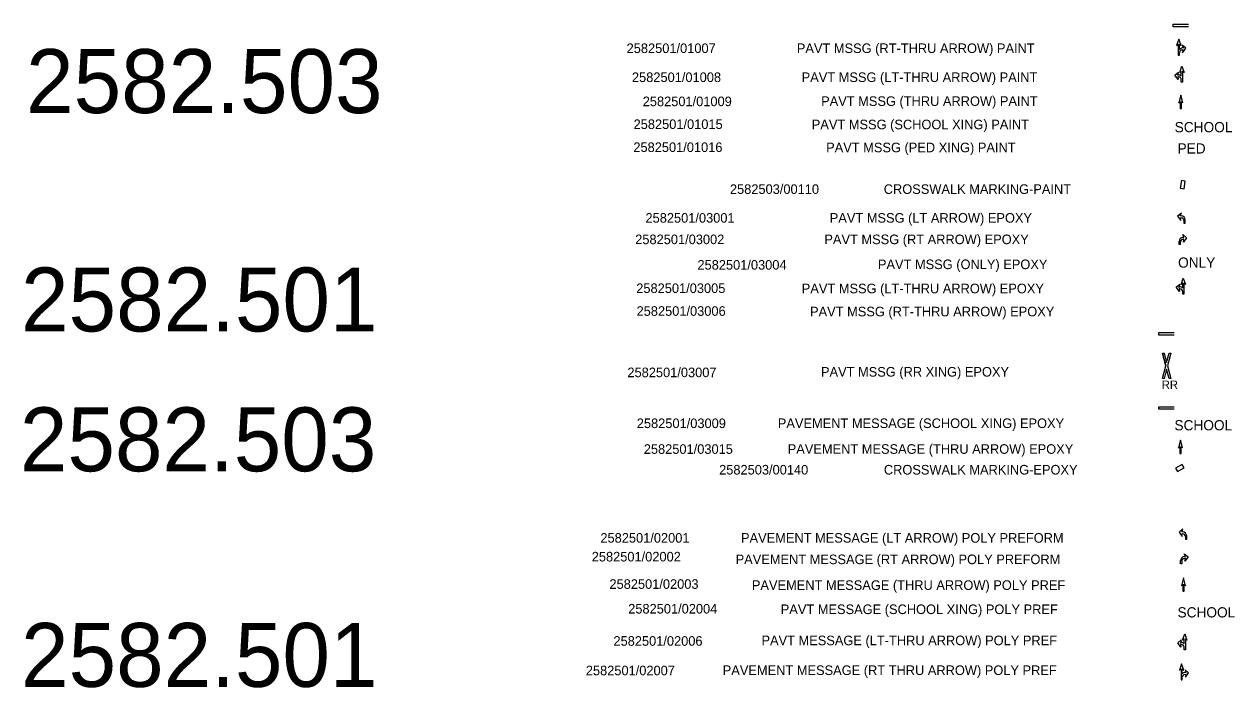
# Model space of a CAD drawing. Extents: x 2147712 to 2176316, y 2125036 to 2131746.
# Drawn here: x 2155867 to 2156814, y 2127331 to 2127850 of the extents above; entities that cross this region are included whole.
import ezdxf

# ---------------------------------------------------------------- set-up
doc = ezdxf.new("R2010")
doc.units = 0
doc.layers.add('DETAIL TXT', color=7, linetype='Continuous')
doc.layers.add('PVMT MARK', color=7, linetype='Continuous')

msp = doc.modelspace()

# ---------------------------------------------------------------- linework, layer by layer
at = {"layer": 'PVMT MARK'}
for p, q in [((2156765.38, 2127850.31), (2156777.38, 2127850.31)), ((2156765.38, 2127848.31), (2156765.38, 2127850.31)), ((2156777.38, 2127848.31), (2156765.38, 2127848.31)), ((2156769.94, 2127838.59), (2156768.21, 2127833.63)), ((2156768.21, 2127833.63), (2156769.45, 2127834.62)), ((2156769.45, 2127834.62), (2156769.45, 2127826.02)), ((2156771.68, 2127833.63), (2156769.94, 2127838.59)), ((2156770.44, 2127830.65), (2156770.44, 2127834.62)), ((2156770.44, 2127834.62), (2156771.68, 2127833.63)), ((2156772.59, 2127830.16), (2156773.25, 2127830.16)), ((2156775.4, 2127831.48), (2156772.66, 2127833.79)), ((2156772.66, 2127833.79), (2156773.32, 2127831.73)), ((2156773.32, 2127831.73), (2156772.66, 2127831.73)), ((2156772.92, 2127828.01), (2156775.4, 2127831.48)), ((2156773.25, 2127830.16), (2156772.92, 2127828.01)), ((2156769.45, 2127826.02), (2156770.44, 2127826.02)), ((2156770.44, 2127826.02), (2156770.44, 2127828.01)), ((2156766.9, 2127810.43), (2156769.65, 2127812.75)), ((2156769.65, 2127812.75), (2156768.99, 2127810.68)), ((2156770.62, 2127812.58), (2156772.36, 2127817.54)), ((2156771.86, 2127813.58), (2156770.62, 2127812.58)), ((2156771.86, 2127809.61), (2156771.86, 2127813.58)), ((2156772.36, 2127817.54), (2156774.1, 2127812.58)), ((2156774.1, 2127812.58), (2156772.86, 2127813.58)), ((2156772.86, 2127813.58), (2156772.86, 2127804.98)), ((2156769.38, 2127806.96), (2156766.9, 2127810.43)), ((2156768.99, 2127810.68), (2156769.65, 2127810.68)), ((2156769.71, 2127809.11), (2156769.05, 2127809.11)), ((2156769.05, 2127809.11), (2156769.38, 2127806.96)), ((2156771.86, 2127804.98), (2156771.86, 2127806.96)), ((2156772.86, 2127804.98), (2156771.86, 2127804.98)), ((2156769.82, 2127788.63), (2156770.95, 2127789.75)), ((2156770.95, 2127789.75), (2156770.95, 2127784.29)), ((2156770.95, 2127784.29), (2156771.94, 2127784.29)), ((2156771.94, 2127784.29), (2156771.94, 2127789.75)), ((2156771.94, 2127789.75), (2156773.06, 2127788.68)), ((2156771.97, 2127702.6), (2156768.99, 2127700.12)), ((2156768.99, 2127700.12), (2156771.47, 2127696.65)), ((2156771.06, 2127700.32), (2156771.97, 2127702.6)), ((2156771.72, 2127700.32), (2156771.06, 2127700.32)), ((2156771.47, 2127696.65), (2156771.06, 2127698.77)), ((2156771.06, 2127698.77), (2156771.72, 2127698.77)), ((2156773.95, 2127696.65), (2156773.95, 2127694.67)), ((2156773.95, 2127694.67), (2156774.94, 2127694.67)), ((2156774.94, 2127694.67), (2156774.94, 2127697.15)), ((2156770.08, 2127677.87), (2156770.08, 2127680.35)), ((2156771.08, 2127679.85), (2156771.08, 2127677.87)), ((2156773.96, 2127683.52), (2156773.06, 2127685.8)), ((2156773.06, 2127685.8), (2156776.04, 2127683.32)), ((2156773.3, 2127683.52), (2156773.96, 2127683.52)), ((2156773.96, 2127681.97), (2156773.3, 2127681.97)), ((2156776.04, 2127683.32), (2156773.56, 2127679.85)), ((2156773.56, 2127679.85), (2156773.96, 2127681.97)), ((2156771.08, 2127677.87), (2156770.08, 2127677.87)), ((2156771.7, 2127646.79), (2156773.43, 2127651.75)), ((2156773.43, 2127651.75), (2156775.17, 2127646.79)), ((2156767.97, 2127644.64), (2156770.72, 2127646.96)), ((2156770.45, 2127641.17), (2156767.97, 2127644.64)), ((2156770.72, 2127646.96), (2156770.06, 2127644.89)), ((2156770.06, 2127644.89), (2156770.72, 2127644.89)), ((2156770.79, 2127643.32), (2156770.12, 2127643.32)), ((2156770.12, 2127643.32), (2156770.45, 2127641.17)), ((2156772.94, 2127647.78), (2156771.7, 2127646.79)), ((2156772.94, 2127643.81), (2156772.94, 2127647.78)), ((2156772.94, 2127639.18), (2156772.94, 2127641.17)), ((2156775.17, 2127646.79), (2156773.93, 2127647.78)), ((2156773.93, 2127647.78), (2156773.93, 2127639.18)), ((2156773.93, 2127639.18), (2156772.94, 2127639.18)), ((2156754.36, 2127609.06), (2156766.36, 2127609.06)), ((2156754.36, 2127607.06), (2156754.36, 2127609.06)), ((2156766.36, 2127607.06), (2156754.36, 2127607.06)), ((2156757.16, 2127593.06), (2156759.76, 2127583.06)), ((2156759.76, 2127583.06), (2156757.16, 2127593.06)), ((2156759.76, 2127583.06), (2156757.16, 2127593.06)), ((2156757.16, 2127593.06), (2156758.46, 2127593.06)), ((2156758.46, 2127593.06), (2156760.36, 2127585.56)), ((2156760.36, 2127585.56), (2156762.36, 2127593.06)), ((2156763.66, 2127593.06), (2156761.06, 2127583.06)), ((2156762.36, 2127593.06), (2156763.66, 2127593.06)), ((2156757.16, 2127573.06), (2156759.76, 2127583.06)), ((2156760.36, 2127580.56), (2156758.46, 2127573.06)), ((2156760.36, 2127583.06), (2156760.36, 2127583.06)), ((2156762.36, 2127573.06), (2156760.36, 2127580.56)), ((2156761.06, 2127583.06), (2156763.66, 2127573.06)), ((2156758.46, 2127573.06), (2156757.16, 2127573.06)), ((2156763.66, 2127573.06), (2156762.36, 2127573.06)), ((2156754.36, 2127551.06), (2156766.36, 2127551.06)), ((2156754.36, 2127549.06), (2156754.36, 2127551.06)), ((2156766.36, 2127549.06), (2156754.36, 2127549.06)), ((2156769.63, 2127518.75), (2156770.76, 2127519.88)), ((2156770.76, 2127519.88), (2156770.76, 2127514.42)), ((2156771.75, 2127514.42), (2156771.75, 2127519.88)), ((2156771.75, 2127519.88), (2156772.87, 2127518.8)), ((2156770.76, 2127514.42), (2156771.75, 2127514.42)), ((2156773.1, 2127455.44), (2156770.12, 2127452.96)), ((2156770.12, 2127452.96), (2156772.6, 2127449.48)), ((2156772.2, 2127453.16), (2156773.1, 2127455.44)), ((2156772.86, 2127453.16), (2156772.2, 2127453.16)), ((2156772.6, 2127449.48), (2156772.2, 2127451.6)), ((2156772.2, 2127451.6), (2156772.86, 2127451.6)), ((2156775.08, 2127449.48), (2156775.08, 2127447.5)), ((2156775.08, 2127447.5), (2156776.08, 2127447.5)), ((2156776.08, 2127447.5), (2156776.08, 2127449.98)), ((2156775.1, 2127433.84), (2156774.19, 2127436.12)), ((2156774.19, 2127436.12), (2156777.17, 2127433.64)), ((2156774.44, 2127433.84), (2156775.1, 2127433.84)), ((2156775.1, 2127432.28), (2156774.44, 2127432.28)), ((2156777.17, 2127433.64), (2156774.69, 2127430.16)), ((2156774.69, 2127430.16), (2156775.1, 2127432.28)), ((2156771.22, 2127428.18), (2156771.22, 2127430.66)), ((2156772.21, 2127428.18), (2156771.22, 2127428.18)), ((2156772.21, 2127430.16), (2156772.21, 2127428.18)), ((2156772.03, 2127411.02), (2156773.15, 2127412.15)), ((2156773.15, 2127412.15), (2156773.15, 2127406.69)), ((2156773.15, 2127406.69), (2156774.14, 2127406.69)), ((2156774.14, 2127406.69), (2156774.14, 2127412.15)), ((2156774.14, 2127412.15), (2156775.27, 2127411.07)), ((2156769.11, 2127366.39), (2156771.85, 2127368.71)), ((2156771.59, 2127362.92), (2156769.11, 2127366.39)), ((2156771.85, 2127368.71), (2156771.19, 2127366.64)), ((2156771.19, 2127366.64), (2156771.85, 2127366.64)), ((2156772.83, 2127368.54), (2156774.56, 2127373.5)), ((2156774.07, 2127369.54), (2156772.83, 2127368.54)), ((2156774.07, 2127365.57), (2156774.07, 2127369.54)), ((2156774.56, 2127373.5), (2156776.3, 2127368.54)), ((2156776.3, 2127368.54), (2156775.06, 2127369.54)), ((2156775.06, 2127369.54), (2156775.06, 2127360.94)), ((2156771.92, 2127365.07), (2156771.26, 2127365.07)), ((2156771.26, 2127365.07), (2156771.59, 2127362.92)), ((2156774.07, 2127360.94), (2156774.07, 2127362.92)), ((2156775.06, 2127360.94), (2156774.07, 2127360.94)), ((2156772.15, 2127350.03), (2156770.41, 2127345.07)), ((2156773.89, 2127345.07), (2156772.15, 2127350.03)), ((2156770.41, 2127345.07), (2156771.65, 2127346.06)), ((2156771.65, 2127346.06), (2156771.65, 2127337.46)), ((2156771.65, 2127337.46), (2156772.65, 2127337.46)), ((2156772.65, 2127342.09), (2156772.65, 2127346.06)), ((2156772.65, 2127346.06), (2156773.89, 2127345.07)), ((2156772.65, 2127337.46), (2156772.65, 2127339.45)), ((2156774.8, 2127341.6), (2156775.46, 2127341.6)), ((2156777.61, 2127342.92), (2156774.86, 2127345.24)), ((2156774.86, 2127345.24), (2156775.52, 2127343.17)), ((2156775.52, 2127343.17), (2156774.86, 2127343.17)), ((2156775.13, 2127339.45), (2156777.61, 2127342.92)), ((2156775.46, 2127341.6), (2156775.13, 2127339.45))]:
    msp.add_line(p, q, dxfattribs=at)
for points in [[(2156773.06, 2127788.68), (2156771.44, 2127794.76), (2156769.82, 2127788.68)], [(2156772.87, 2127518.8), (2156771.25, 2127524.88), (2156769.63, 2127518.8)], [(2156775.27, 2127411.07), (2156773.65, 2127417.16), (2156772.03, 2127411.07)]]:
    msp.add_lwpolyline(points, dxfattribs=at)
for points in [[(2156771.05, 2127722.07), (2156774.01, 2127721.57), (2156775, 2127727.49), (2156772.04, 2127727.98)], [(2156774.11, 2127503.34), (2156772.66, 2127505.97), (2156767.41, 2127503.05), (2156768.87, 2127500.43)]]:
    msp.add_lwpolyline(points, close=True, dxfattribs=at)
for radius in [0.04, 0.035]:
    msp.add_circle((2156760.36, 2127583.06), radius, dxfattribs=at)
for centre, radius, start, end in [((2156772.85, 2127828.51), 3.22, 93.44933, 138.32895), ((2156772.59, 2127828.01), 2.15, 90, 180), ((2156769.45, 2127807.46), 3.22, 41.67105, 86.55067), ((2156769.71, 2127806.96), 2.15, 0, 90), ((2156771.72, 2127697.1), 3.22, 0.85489, 89.91229), ((2156771.8, 2127696.62), 2.15, 0.74176, 90.20562), ((2156773.31, 2127680.3), 3.22, 90.08771, 179.14511), ((2156773.22, 2127679.82), 2.15, 89.79438, 179.25824), ((2156770.53, 2127641.67), 3.22, 41.67105, 86.55067), ((2156770.79, 2127641.17), 2.15, 0, 90), ((2156772.85, 2127449.93), 3.22, 0.85489, 89.91229), ((2156772.93, 2127449.46), 2.15, 0.74176, 90.20562), ((2156774.44, 2127430.61), 3.22, 90.08771, 179.14511), ((2156774.36, 2127430.14), 2.15, 89.79438, 179.25824), ((2156771.66, 2127363.42), 3.22, 41.67105, 86.55067), ((2156771.92, 2127362.92), 2.15, 0, 90), ((2156775.05, 2127339.95), 3.22, 93.44933, 138.32895), ((2156774.8, 2127339.45), 2.15, 90, 180)]:
    msp.add_arc(centre, radius, start, end, dxfattribs=at)

# ---------------------------------------------------------------- texts
at = {"layer": 'DETAIL TXT'}
for s, height, p in [('2582.503', 50, (2155868.02, 2127780.79)), ('2582501/01007', 7.5, (2156337.86, 2127827.76)), ('PAVT MSSG (RT-THRU ARROW) PAINT', 7.5, (2156471.04, 2127827.76)), ('2582501/01008', 7.5, (2156342.04, 2127805.09)), ('PAVT MSSG (LT-THRU ARROW) PAINT', 7.5, (2156474.82, 2127805.09)), ('2582501/01009', 7.5, (2156350.45, 2127786.19)), ('PAVT MSSG (THRU ARROW) PAINT', 7.5, (2156490.06, 2127786.4)), ('2582501/01015', 7.5, (2156343.31, 2127768.34)), ('PAVT MSSG (SCHOOL XING) PAINT', 7.5, (2156482.74, 2127768.13)), ('2582501/01016', 7.5, (2156343.13, 2127750.34)), ('PAVT MSSG (PED XING) PAINT', 7.5, (2156493.99, 2127750.13)), ('2582503/00110', 7.5, (2156418.7, 2127717.55)), ('CROSSWALK MARKING-PAINT', 7.5, (2156539.05, 2127717.55)), ('2582501/03001', 7.5, (2156352.62, 2127695.05)), ('PAVT MSSG (LT ARROW) EPOXY', 7.5, (2156496.81, 2127695.05)), ('2582501/03002', 7.5, (2156344.58, 2127678.25)), ('PAVT MSSG (RT ARROW) EPOXY', 7.5, (2156492.61, 2127678.25)), ('2582.501', 50, (2155864.06, 2127609.96)), ('2582501/03004', 7.5, (2156393.28, 2127658.3)), ('PAVT MSSG (ONLY) EPOXY', 7.5, (2156534.49, 2127658.72)), ('2582501/03005', 7.5, (2156345.41, 2127640.03)), ('PAVT MSSG (LT-THRU ARROW) EPOXY', 7.5, (2156474.91, 2127639.82)), ('2582501/03006', 7.5, (2156345.65, 2127622.19)), ('PAVT MSSG (RT-THRU ARROW) EPOXY', 7.5, (2156481.39, 2127621.77)), ('2582501/03007', 7.5, (2156338.49, 2127574.18)), ('PAVT MSSG (RR XING) EPOXY', 7.5, (2156489.95, 2127574.64)), ('2582.503', 50, (2155863.16, 2127500.56)), ('2582501/03009', 7.5, (2156345.83, 2127534.37)), ('PAVEMENT MESSAGE (SCHOOL XING) EPOXY', 7.5, (2156456.16, 2127534.4)), ('2582501/03015', 7.5, (2156351.29, 2127514.21)), ('PAVEMENT MESSAGE (THRU ARROW) EPOXY', 7.5, (2156463.9, 2127514.24)), ('2582503/00140', 7.5, (2156410.24, 2127498.04)), ('CROSSWALK MARKING-EPOXY', 7.5, (2156539.14, 2127498.04)), ('2582501/02001', 7.5, (2156317.34, 2127444.73)), ('PAVEMENT MESSAGE (LT ARROW) POLY PREFORM', 7.5, (2156427.35, 2127444.73)), ('2582501/02002', 7.5, (2156310.56, 2127430.03)), ('PAVEMENT MESSAGE (RT ARROW) POLY PREFORM', 7.5, (2156423.15, 2127427.93)), ('2582501/02003', 7.5, (2156324.42, 2127408.61)), ('PAVEMENT MESSAGE (THRU ARROW) POLY PREF', 7.5, (2156435.87, 2127407.77)), ('2582501/02004', 7.5, (2156339.1, 2127389.29)), ('PAVT MESSAGE (SCHOOL XING) POLY PREF', 7.5, (2156458.46, 2127388.87)), ('2582.501', 50, (2155864.06, 2127331.92)), ('2582501/02006', 7.5, (2156327.56, 2127364.09)), ('PAVT MESSAGE (LT-THRU ARROW) POLY PREF', 7.5, (2156443.4, 2127364.51)), ('2582501/02007', 7.5, (2156305.94, 2127340.99)), ('PAVEMENT MESSAGE (RT THRU ARROW) POLY PREF', 7.5, (2156413.07, 2127341.2))]:
    msp.add_text(s, height=height, dxfattribs=at).set_placement(p)
at = {"layer": 'PVMT MARK'}
for s, p in [('PERIMETER 50FT', (2156772.86, 2127830.85)), ('AREA 26 SQ FT', (2156772.97, 2127831.3)), ('REM 95 SQ FT', (2156773.03, 2127831.09)), ("PERIMETER = 30 '", (2156771.83, 2127682.17)), ("REM = 48 SQ '", (2156772.09, 2127682.49)), ("AREA = 15 SQ'", (2156772.19, 2127682.82)), ("PERIMETER = 30 '", (2156772.96, 2127432.48)), ("REM = 48 SQ '", (2156773.22, 2127432.8)), ("AREA = 15 SQ'", (2156773.32, 2127433.13)), ('PERIMETER 50FT', (2156775.06, 2127342.29)), ('AREA 26 SQ FT', (2156775.17, 2127342.74)), ('REM 95 SQ FT', (2156775.23, 2127342.53))]:
    msp.add_text(s, height=0.0992, rotation=360, dxfattribs=at).set_placement(p)
for s, height, p in [('AREA 26 SQ FT', 0.0992, (2156768.14, 2127810.26)), ('REM 95 SQ FT', 0.0992, (2156768.17, 2127810.05)), ('PERIMETER 50FT', 0.0992, (2156768.2, 2127809.8)), ('PERIMETER 30 FT', 0.0907, (2156770.68, 2127790.4)), ('REM 35 SF', 0.0907, (2156770.93, 2127790.74)), ('AREA 15 SF', 0.0907, (2156771.01, 2127791.04)), ('SCHOOL', 8, (2156766.69, 2127765.8)), ('PED', 8, (2156768.91, 2127749.13)), ("AREA = 15 SQ'", 0.0992, (2156771.77, 2127699.69)), ("REM = 48 SQ '", 0.0992, (2156771.83, 2127699.36)), ("PERIMETER = 30 '", 0.0992, (2156771.85, 2127699.04)), ('ONLY', 8, (2156769.36, 2127659.85)), ('AREA 26 SQ FT', 0.0992, (2156769.21, 2127644.46)), ('REM 95 SQ FT', 0.0992, (2156769.24, 2127644.25)), ('PERIMETER 50FT', 0.0992, (2156769.27, 2127644.01)), ('RR', 6.5, (2156756.66, 2127565.06)), ('SCHOOL', 8, (2156766.5, 2127532.59)), ('PERIMETER 30 FT', 0.0907, (2156770.5, 2127520.52)), ('REM 35 SF', 0.0907, (2156770.74, 2127520.86)), ('AREA 15 SF', 0.0907, (2156770.83, 2127521.16)), ("AREA = 15 SQ'", 0.0992, (2156772.91, 2127452.52)), ("REM = 48 SQ '", 0.0992, (2156772.96, 2127452.2)), ("PERIMETER = 30 '", 0.0992, (2156772.98, 2127451.87)), ('REM 35 SF', 0.0907, (2156773.13, 2127413.13)), ('AREA 15 SF', 0.0907, (2156773.22, 2127413.43)), ('PERIMETER 30 FT', 0.0907, (2156772.89, 2127412.79)), ('SCHOOL', 8, (2156768.9, 2127386.23)), ('AREA 26 SQ FT', 0.0992, (2156770.35, 2127366.22)), ('REM 95 SQ FT', 0.0992, (2156770.37, 2127366.01)), ('PERIMETER 50FT', 0.0992, (2156770.4, 2127365.76))]:
    msp.add_text(s, height=height, dxfattribs=at).set_placement(p)

doc.saveas('drawing.dxf')
